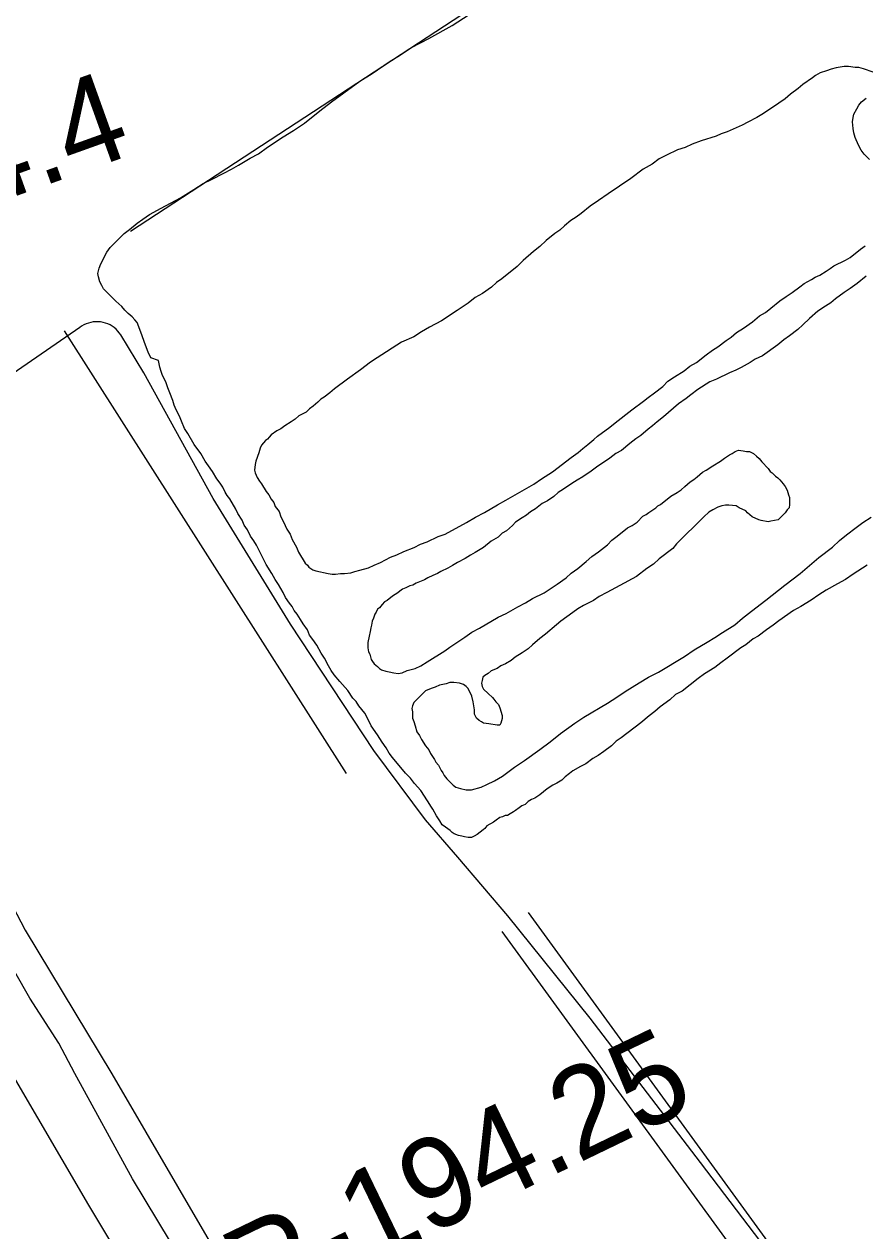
# Model space of a CAD drawing. Extents: x 3324125 to 3362000, y 600753 to 626151.
# Drawn here: x 3331430 to 3332206, y 613099 to 614214 of the extents above; entities that cross this region are included whole.
import ezdxf

# ---------------------------------------------------------------- set-up
doc = ezdxf.new("R2010")
doc.units = 0
for name, color, linetype in [('V-DTCH-CNTR', 7, 'Continuous'), ('V-RIVR-RANG-IDEN', 7, 'Continuous'), ('V-ROAD-CNTR', 7, 'Continuous'), ('V-SITE-VEGE', 7, 'Continuous'), ('V-TOPO-SHOR', 7, 'Continuous')]:
    doc.layers.add(name, color=color, linetype=linetype)

msp = doc.modelspace()

# ---------------------------------------------------------------- linework, layer by layer
at = {"layer": 'V-DTCH-CNTR'}
for points in [[(3330957.7, 614274.3), (3331010.7, 614177.8), (3331082.2, 614037.5), (3331152.6, 613902.5), (3331209.1, 613797.3), (3331231.5, 613760.5), (3331290.9, 613648.4), (3331372.2, 613487.5), (3331430.4, 613376.6), (3331510.5, 613243.8), (3331602.7, 613085.8)], [(3332148.2, 613038.2), (3332054.3, 613161.7), (3331952.4, 613295), (3331876.3, 613389.8), (3331830.2, 613443.8), (3331800.3, 613478.3), (3331752.5, 613542.6), (3331675.6, 613659.3), (3331604.1, 613775.3), (3331540.1, 613891.4), (3331518.8, 613926.5), (3331517.5, 613928.4), (3331516.1, 613930.1), (3331514.5, 613931.8), (3331512.7, 613933.2), (3331510.9, 613934.6), (3331508.9, 613935.7), (3331506.8, 613936.7), (3331504.7, 613937.5), (3331502.5, 613938.1), (3331500.2, 613938.5), (3331498, 613938.7), (3331495.7, 613938.7), (3331493.4, 613938.5), (3331491.1, 613938.1), (3331488.9, 613937.5), (3331486.8, 613936.8), (3331484.7, 613935.8), (3331482.7, 613934.6), (3331480.9, 613933.3), (3331307.9, 613814.1)]]:
    msp.add_lwpolyline(points, dxfattribs=at)
at = {"layer": 'V-ROAD-CNTR'}
for points in [[(3328654.4, 618531.3), (3329365.9, 617157.1), (3329945, 616043.4), (3330528.3, 614922), (3330989.5, 614026.8), (3331101.4, 613813.5), (3331202.1, 613623.7), (3331288.2, 613468), (3331370, 613325.9), (3331489, 613122.4), (3331566.5, 612992.9), (3331683.8, 612804.9), (3331896.1, 612486.7), (3332030.8, 612296.1), (3332261.4, 611985.3), (3332414.1, 611792.3), (3332593.4, 611567.9), (3332751.8, 611383.2), (3332947.9, 611162.2), (3333176.2, 610911.4), (3333408.7, 610672.1), (3333754.4, 610344.1), (3333997.3, 610124.4), (3334416.3, 609777.9)], [(3331895.2, 613392.7), (3332218.1, 612948.7)], [(3331870.9, 613375.1), (3332194, 612930.9)]]:
    msp.add_lwpolyline(points, dxfattribs=at)
at = {"layer": 'V-SITE-VEGE'}
for points in [[(3331603.5, 613800.2), (3331599.9, 613805.5), (3331596.9, 613809.7), (3331592.7, 613816.9), (3331586.7, 613825.2), (3331580.8, 613835.4), (3331577.8, 613840.1), (3331574.8, 613846.7), (3331573, 613851.5), (3331570, 613857.4), (3331568.2, 613861.6), (3331567, 613865.8), (3331564, 613872.9), (3331562.2, 613877.7), (3331560.4, 613883.1), (3331557.4, 613889.1), (3331556.2, 613892.6), (3331555, 613896.8), (3331553.8, 613902.8), (3331546.6, 613905.2), (3331544.2, 613910.5), (3331540.6, 613919.5), (3331538.2, 613926.6), (3331534.1, 613938), (3331531.7, 613940.4), (3331529.3, 613943.3), (3331525.7, 613946.3), (3331522.7, 613949.3), (3331519.7, 613952.9), (3331514.3, 613957.7), (3331503, 613969), (3331501.2, 613972), (3331499.4, 613975.5), (3331498.2, 613980.3), (3331497.6, 613983.3), (3331498.8, 613988.1), (3331500.5, 613992.3), (3331505.9, 614003), (3331508.9, 614007.2), (3331522, 614020.3), (3331526.8, 614023.9), (3331533.9, 614029.9), (3331539.3, 614033.5), (3331545.3, 614037.7), (3331556, 614043.7), (3331573.9, 614053.2), (3331586.4, 614061), (3331594.8, 614066.4), (3331602.5, 614070), (3331613.9, 614076), (3331621, 614079.6), (3331627.6, 614083.2), (3331638.3, 614089.7), (3331646.1, 614093.9), (3331654.4, 614099.9), (3331668.7, 614109.5), (3331678.3, 614115.5), (3331688.4, 614122.1), (3331702.7, 614133.4), (3331713.5, 614141.8), (3331739.7, 614160.9), (3331751.1, 614168.1), (3331766.6, 614178.9), (3331777.3, 614185.4), (3331787.4, 614192), (3331803.5, 614200.4), (3331825, 614212.4), (3331840.5, 614222.5)], [(3332213.7, 614169.3), (3332204.8, 614172.3), (3332200.6, 614173.5), (3332197, 614173.5), (3332191, 614174.6), (3332186.8, 614174.6), (3332179.7, 614173.4), (3332174.9, 614172.2), (3332170.7, 614170.4), (3332164.8, 614168.6), (3332160.6, 614166.3), (3332157.6, 614163.9), (3332148.7, 614157.9), (3332144.5, 614154.3), (3332137.3, 614148.9), (3332132.6, 614144.7), (3332126.6, 614140.5), (3332112.3, 614131), (3332106.3, 614127.4), (3332098, 614123.2), (3332092.6, 614120.2), (3332078.9, 614114.2), (3332073.5, 614112.4), (3332068.7, 614110), (3332055, 614105.8), (3332046.6, 614102.8), (3332040.1, 614099.8), (3332032.9, 614097.4), (3332022.8, 614092.6), (3332016.2, 614089.1), (3332009.7, 614084.3), (3332001.3, 614079.5), (3331990, 614071.1)], [(3332210.2, 614088.7), (3332205.5, 614093.5), (3332202.5, 614097.1), (3332200.1, 614101.8), (3332197.1, 614109), (3332195.9, 614113.2), (3332195.3, 614117.3), (3332194.7, 614123.3), (3332195.3, 614127.5), (3332195.9, 614130.5), (3332198.8, 614135.3), (3332200.6, 614138.8), (3332203, 614141.8), (3332207.2, 614145.4)], [(3331990, 614071.1), (3331969.1, 614056.8), (3331960.1, 614050.8), (3331952.4, 614045.4), (3331944, 614038.8), (3331939.3, 614035.2), (3331934.5, 614032.2), (3331928.5, 614027.4), (3331924.4, 614023.3), (3331919.6, 614020.3), (3331911.8, 614013.7), (3331905.9, 614008.3), (3331899.9, 614003.5), (3331890.4, 613995.2), (3331885, 613989.8), (3331870.7, 613978.4), (3331865.9, 613974.8), (3331861.2, 613970.6), (3331852.8, 613964.7), (3331846.2, 613961.1), (3331839.7, 613955.7), (3331829.5, 613949.1), (3331815.2, 613939.5), (3331803.9, 613933.6), (3331796.7, 613929.4), (3331789.6, 613924.6), (3331778.2, 613919.8), (3331755.6, 613905.4), (3331749.6, 613901.2), (3331740.1, 613894.1), (3331728.1, 613885.7), (3331716.2, 613876.7), (3331712, 613873.1), (3331706.7, 613869), (3331703.7, 613867.2), (3331700.7, 613864.2), (3331696.5, 613860.6), (3331693, 613858.2), (3331690, 613855.2), (3331683.4, 613851.6), (3331679.8, 613848.6), (3331676.3, 613846.2), (3331670.3, 613842.6), (3331666.7, 613839.7), (3331663.1, 613837.9), (3331657.8, 613834.3), (3331656, 613831.9), (3331654.2, 613830.1), (3331652.4, 613828.9), (3331648.8, 613824.7), (3331647.6, 613821.7), (3331646.4, 613817.5), (3331643.5, 613809.8), (3331642.9, 613806.8), (3331642.3, 613801.4), (3331642.9, 613799), (3331644.7, 613794.8), (3331647.1, 613791.3), (3331648.9, 613788.9), (3331653.1, 613781.7), (3331655.5, 613778.7), (3331657.8, 613774.6), (3331660.2, 613771.6), (3331661.4, 613768), (3331665, 613763.2), (3331666.8, 613758.5), (3331669.2, 613753.7), (3331672.2, 613747.1), (3331675.2, 613742.4), (3331677, 613737.6), (3331681.2, 613730.4), (3331683, 613725.7), (3331689, 613715.5), (3331691.4, 613713.7), (3331692.5, 613711.9), (3331696.1, 613709.5), (3331699.1, 613708.4), (3331710.5, 613706), (3331714, 613705.4), (3331717, 613705.4), (3331721.8, 613706), (3331725.4, 613706), (3331731.4, 613706.6), (3331734.9, 613707.8), (3331739.7, 613709), (3331747.5, 613711.4), (3331752.8, 613713.8), (3331758.8, 613716.2), (3331767.8, 613721), (3331773.7, 613723.4), (3331780.3, 613726.4), (3331789.8, 613730), (3331795.8, 613733), (3331801.8, 613735.4), (3331811.9, 613740.1), (3331818.5, 613742.5), (3331838.2, 613753.3), (3331846.5, 613758.1), (3331854.9, 613762.3), (3331866.8, 613769.5), (3331874.5, 613773.7)], [(3331874.5, 613773.7), (3331900.2, 613788.6), (3331907.4, 613793.4), (3331917.5, 613800), (3331934.8, 613813.1), (3331941.3, 613817.9), (3331945.5, 613821.5), (3331950.3, 613825.1), (3331955.7, 613829.9), (3331959.2, 613832.9), (3331970.6, 613841.2), (3331975.3, 613845.4), (3331990.8, 613857.4), (3332001.6, 613865.2), (3332005.8, 613868.8), (3332011.7, 613872.9), (3332019.5, 613878.9), (3332024.2, 613883.7), (3332030.2, 613887.9), (3332039.2, 613893.3), (3332044.5, 613897.5), (3332050.5, 613901), (3332059.4, 613908.2), (3332065.4, 613912.4), (3332070.2, 613915.4), (3332077.9, 613921.4), (3332082.7, 613924.4), (3332087.5, 613928.6), (3332094, 613932.7), (3332102.4, 613938.7), (3332108.9, 613944.1), (3332114.3, 613947.1), (3332119.1, 613951.3), (3332127.4, 613957.9), (3332133.4, 613962), (3332138.8, 613965.6), (3332145.9, 613971), (3332150.1, 613974), (3332156.7, 613977.6), (3332160.2, 613980), (3332164.4, 613981.8), (3332170.4, 613985.4), (3332174, 613987.8), (3332177.5, 613990.2), (3332188.3, 613995.6), (3332192.4, 613997.9), (3332202, 614005.7), (3332206.2, 614008.7)], [(3332207.4, 613980.7), (3332199, 613974.1), (3332192.5, 613969.3), (3332187.1, 613965.7), (3332178.8, 613959.7), (3332174.6, 613956.1), (3332169.8, 613953.1), (3332162.7, 613948.4), (3332154.9, 613941.8), (3332148.9, 613935.8), (3332144.2, 613931.6), (3332136.4, 613925.6), (3332131.1, 613922), (3332125.7, 613917.3), (3332111.4, 613907.1), (3332104.8, 613904.1), (3332100, 613901.1), (3332091.7, 613896.3), (3332086.9, 613893.9), (3332080.9, 613891.5), (3332069, 613885.6), (3332063, 613883.2), (3332051.7, 613876), (3332045.2, 613871.2), (3332041, 613867.6), (3332033.8, 613862.8), (3332020.1, 613850.9), (3332014.1, 613846.1), (3332010, 613842.5), (3332005.8, 613839.5), (3331999.2, 613833.5), (3331994.5, 613830.5)], [(3331994.5, 613830.5), (3331989.1, 613826.3), (3331981.3, 613819.8), (3331976, 613816.8), (3331970.6, 613812.6), (3331958.1, 613804.2), (3331953.3, 613800.6), (3331945.6, 613795.2), (3331940.2, 613792.3), (3331935.4, 613789.3), (3331927.7, 613783.9), (3331922.9, 613780.9), (3331918.7, 613777.3), (3331912.8, 613773.1), (3331908, 613770.7), (3331902, 613765.9), (3331897.2, 613762.9), (3331893.7, 613760), (3331889.5, 613757.6), (3331883.5, 613753.4), (3331880.5, 613750.4), (3331875.2, 613745.6), (3331871, 613743.2), (3331867.4, 613739.6), (3331860.9, 613736), (3331853.7, 613730.1), (3331846, 613725.3), (3331841.8, 613722.9), (3331837, 613719.9), (3331829.8, 613716.3), (3331825.1, 613713.3), (3331820.9, 613710.9), (3331814.3, 613707.9), (3331811.4, 613706.1), (3331807.2, 613704.3), (3331802.4, 613701.9), (3331799.4, 613700.1), (3331791.7, 613697.1), (3331788.7, 613695.3), (3331785.7, 613694.7), (3331782.1, 613692.9), (3331779.1, 613691.7), (3331773.8, 613687.6), (3331770.8, 613685.8), (3331768.4, 613684), (3331764.8, 613681), (3331762.4, 613679.8), (3331760.1, 613677.4), (3331757.7, 613674.4), (3331755.9, 613673.2), (3331754.7, 613670.2), (3331753.5, 613668.4), (3331752.3, 613664.9), (3331751.1, 613661.9), (3331750.5, 613658.3), (3331749.9, 613655.9), (3331749.3, 613652.3), (3331748.2, 613648.1), (3331747, 613642.2), (3331747, 613637.4), (3331747.6, 613633.8), (3331748.8, 613631.4), (3331750, 613626.6), (3331751.2, 613624.8), (3331753, 613622.5), (3331755.9, 613620.1), (3331757.7, 613618.3), (3331759.5, 613617.1), (3331763.7, 613615.9), (3331766.7, 613615.3), (3331770.9, 613614.1), (3331775.1, 613613.5), (3331778.6, 613614.1), (3331783.4, 613616.5), (3331790.6, 613618.3), (3331795.9, 613620.7), (3331801.9, 613624.3), (3331818, 613634.5), (3331822.8, 613638.1), (3331828.2, 613641.7), (3331836.5, 613647.1), (3331843.1, 613651.8), (3331850.2, 613655.4), (3331867.5, 613665.6), (3331874.7, 613669.2), (3331885.4, 613675.2), (3331892.6, 613678.8), (3331899.1, 613682.9), (3331909.9, 613688.3), (3331916.4, 613692.5), (3331921.8, 613696.1), (3331930.2, 613702.1), (3331934.9, 613706.3), (3331940.9, 613710.5), (3331948.6, 613717), (3331954, 613721.8), (3331960, 613726), (3331968.3, 613732.6), (3331972.5, 613736.8), (3331977.3, 613740.4), (3331986.8, 613748.1)], [(3331986.8, 613748.1), (3331991, 613750.5), (3331995.8, 613753.5), (3332001.1, 613758.9), (3332004.1, 613760.7), (3332006.5, 613762.5), (3332010.1, 613764.9), (3332013.1, 613766.7), (3332014.8, 613768.5), (3332017.2, 613769.7), (3332026.8, 613777.4), (3332032.7, 613781), (3332036.3, 613783.4), (3332039.9, 613786.4), (3332044.7, 613790.6), (3332048.2, 613793), (3332051.2, 613795.4), (3332056, 613799.6), (3332059.6, 613801.4), (3332065.5, 613805.6), (3332072.7, 613809.7), (3332076.3, 613812.7), (3332081, 613815.7), (3332083.4, 613816.9), (3332086.4, 613818.7), (3332089.4, 613819.9), (3332093.6, 613819.3), (3332096.6, 613818.7), (3332099.6, 613818.7), (3332103.1, 613816.9), (3332106.1, 613814.6), (3332108.5, 613812.2), (3332110.9, 613809.2), (3332116.9, 613803.2), (3332118.7, 613800.2), (3332120.5, 613799.1), (3332123.5, 613796.1), (3332125.8, 613794.3), (3332127.6, 613792.5), (3332130.6, 613788.9), (3332132.4, 613786.5), (3332134.2, 613783), (3332135.4, 613778.8), (3332136.6, 613776.4), (3332136.6, 613769.8), (3332136, 613766.8), (3332134.2, 613765), (3332132.5, 613762.1), (3332125.9, 613755.5), (3332119.3, 613754.3), (3332116.9, 613753.7), (3332110.4, 613754.9), (3332108, 613755.5), (3332102, 613758.4), (3332097.8, 613762), (3332096, 613763.8), (3332090.1, 613766.8), (3332087.1, 613768.6), (3332080.5, 613769.2), (3332077.5, 613769.1), (3332073.9, 613768.5), (3332070.4, 613767.3), (3332065.6, 613765), (3332062, 613762.6), (3332057.2, 613758.4), (3332032.2, 613733.3), (3332028.6, 613729.1), (3332016.1, 613719.5), (3332010.7, 613714.7), (3332004.8, 613710.6), (3331995.2, 613703.4), (3331979.7, 613695), (3331967.8, 613688.4), (3331960.6, 613684.8), (3331955.3, 613681.2), (3331946.3, 613676.4), (3331940.9, 613673.5), (3331936.2, 613669.9), (3331925.4, 613662.1), (3331921.3, 613658.5), (3331911.1, 613650.1), (3331905.8, 613645.9), (3331899.2, 613640), (3331895, 613636.4), (3331889.7, 613632.8), (3331883.1, 613628.6), (3331879.5, 613625.6), (3331874.1, 613622.6), (3331870, 613620.8), (3331866.4, 613618.4), (3331861, 613616), (3331858, 613613.6), (3331855.1, 613611.9), (3331853.3, 613610.1), (3331852.7, 613607.1), (3331852.1, 613604.7), (3331852.7, 613601.7), (3331853.9, 613599.3), (3331858.1, 613595.1), (3331862.3, 613591.6), (3331863.4, 613589.8)], [(3331965, 613541.6), (3331959.6, 613538), (3331954.9, 613535), (3331948.3, 613530.2), (3331943.5, 613527.8), (3331936.4, 613523.6), (3331933.4, 613521.2), (3331929.2, 613518.2), (3331926.2, 613515.2), (3331921.5, 613512.2), (3331917.9, 613510.4), (3331912.5, 613506.9), (3331905.9, 613501.5), (3331901.2, 613498.5), (3331898.2, 613497.3), (3331895.2, 613495.5), (3331892.2, 613492.5), (3331889.2, 613491.3), (3331886.9, 613489.5), (3331883.3, 613487.1), (3331881.5, 613485.9), (3331878.5, 613484.1), (3331876.1, 613482.3), (3331873.7, 613482.3), (3331871.4, 613481.1), (3331869, 613480.5), (3331865.4, 613478.1), (3331863, 613476.3), (3331857, 613472.8), (3331855.2, 613470.4), (3331853.5, 613469.2), (3331848.1, 613465), (3331845.1, 613463.2), (3331842.7, 613462), (3331839.7, 613462), (3331836.2, 613462.6), (3331833.8, 613463.2), (3331830.8, 613463.8), (3331826.6, 613465.6), (3331824.8, 613466.7), (3331823, 613468.5), (3331818.8, 613471.5), (3331815.8, 613473.9), (3331813.4, 613477.5), (3331810.5, 613482.2), (3331806.9, 613488.2), (3331805.7, 613490), (3331802.1, 613496), (3331796.1, 613505.5), (3331790.1, 613512.1), (3331786.5, 613516.8), (3331781.8, 613521.6), (3331769.8, 613535.9), (3331766.8, 613540.1), (3331763.8, 613544.9), (3331760.2, 613550.2), (3331756, 613556.8), (3331750.1, 613565.2), (3331747.1, 613571.7), (3331744.1, 613577.1), (3331738.7, 613583.6), (3331736.3, 613587.8), (3331733.3, 613590.8), (3331728.5, 613598), (3331721.3, 613606.3), (3331716, 613612.3), (3331713, 613616.4), (3331710.6, 613620.6), (3331707, 613627.8), (3331704, 613632.5), (3331699.8, 613639.7), (3331696.2, 613645.1), (3331693.2, 613649.2), (3331691.4, 613654), (3331687.2, 613659.4), (3331684.9, 613663.6), (3331681.9, 613668.3), (3331678.9, 613671.9), (3331677.1, 613675.5), (3331674.7, 613678.5), (3331671.1, 613683.8), (3331668.7, 613688.6), (3331664.5, 613695.8), (3331661.5, 613700.5), (3331658.5, 613705.9), (3331653.1, 613714.3), (3331644.2, 613732.2), (3331641.8, 613736.3), (3331638.8, 613740.5), (3331635.8, 613746.5), (3331632.8, 613750.7), (3331631, 613755.4), (3331626.8, 613761.4), (3331625, 613765.6), (3331619.6, 613775.1), (3331617.2, 613778.1), (3331615.4, 613781.1), (3331613.1, 613785.9), (3331610.7, 613789.4), (3331607.7, 613793.6), (3331603.5, 613800.2)], [(3331863.4, 613589.8), (3331865.2, 613587.4), (3331867.6, 613585), (3331868.8, 613582), (3331871.2, 613574.9), (3331871.2, 613571.9), (3331870, 613567.7), (3331868.9, 613565.9), (3331866.5, 613565.9), (3331858.7, 613567.1), (3331853.9, 613567.7), (3331852.1, 613568.9), (3331849.7, 613570.1), (3331847.4, 613572.4), (3331845.6, 613576), (3331845.5, 613580.2), (3331844.3, 613587.4), (3331843.1, 613592.7), (3331839.6, 613599.9), (3331837.8, 613601.7), (3331835.4, 613603.5), (3331831.8, 613604.7), (3331826.4, 613605.2), (3331822.8, 613605.2), (3331819.3, 613604), (3331813.3, 613602.8), (3331809.1, 613601), (3331805.5, 613599.8), (3331800.2, 613597.5), (3331789.4, 613586.7), (3331788.2, 613583.7), (3331787.6, 613581.3), (3331788.2, 613578.3), (3331788.2, 613572.4), (3331789.4, 613569.4), (3331790.6, 613565.2), (3331792.4, 613559.8), (3331794.8, 613556.3), (3331796.6, 613552.7), (3331800.2, 613546.7), (3331803.2, 613543.1), (3331805, 613539.6), (3331808.6, 613534.2), (3331809.8, 613531.8), (3331812.2, 613528.8), (3331814.6, 613524), (3331816.4, 613521.7), (3331817.6, 613519.3), (3331820, 613516.3), (3331825.9, 613510.3), (3331828.3, 613508.5), (3331832.5, 613507.4), (3331837.9, 613506.2), (3331842.7, 613506.2), (3331851.6, 613508.6), (3331857, 613511), (3331864.1, 613514.6), (3331871.3, 613518.7), (3331882.6, 613527.1), (3331891.6, 613533.1), (3331905.9, 613543.3), (3331915.4, 613550.4), (3331925, 613558.2), (3331938.1, 613567.8), (3331946.4, 613573.2), (3331968.5, 613586.3), (3331976.9, 613591.7), (3331984.6, 613597.1), (3331997.7, 613604.9), (3332006.1, 613610.3), (3332015.6, 613615), (3332039.5, 613629.4), (3332048.5, 613635.4), (3332060.4, 613642.6), (3332067.5, 613646.8), (3332074.7, 613651.5), (3332086, 613658.7), (3332093.2, 613664.7), (3332101.5, 613671.3), (3332114.7, 613681.4), (3332132, 613695.2), (3332146.3, 613706), (3332163.6, 613720.9), (3332176.1, 613730.5), (3332182.6, 613736.5), (3332189.2, 613741.8), (3332198.1, 613748.4), (3332204.1, 613753.2), (3332211.9, 613758)], [(3332208.3, 613713.8), (3332195.2, 613705.4), (3332188.1, 613700.6), (3332180.9, 613696.5), (3332170.2, 613690.5), (3332163.6, 613686.3), (3332156.4, 613681.5), (3332146.9, 613675.5), (3332140.3, 613671.9), (3332126.6, 613662.4), (3332121.3, 613658.2), (3332115.3, 613654), (3332107.5, 613648), (3332102.8, 613645.6), (3332096.2, 613640.2), (3332091.4, 613637.2), (3332078.9, 613627.7), (3332072.9, 613623.5), (3332067.6, 613619.3), (3332058, 613613.3), (3332052.1, 613609.1), (3332037.2, 613597.2), (3332031.2, 613594.2), (3332025.8, 613589.4), (3332016.9, 613582.8), (3332012.1, 613578.6), (3332006.7, 613574.4), (3331999, 613567.9), (3331981.1, 613554.1), (3331976.3, 613551.1), (3331972.2, 613546.9), (3331965, 613541.6)]]:
    msp.add_lwpolyline(points, dxfattribs=at)
at = {"layer": 'V-TOPO-SHOR'}
for p, q in [((3331527.7, 614022.3), (3332519.7, 614671.7)), ((3331466.4, 613930.3), (3331727.1, 613521.2))]:
    msp.add_line(p, q, dxfattribs=at)
msp.add_lwpolyline([(3331854.7, 612684.6), (3331838.4, 612673.6), (3331836.3, 612674.3), (3331751, 612789.3), (3331652.7, 612945.9), (3331632.2, 612984.7), (3331598.8, 613031.7), (3331529.8, 613146.7), (3331476.5, 613244.1), (3331461.5, 613272), (3331434.9, 613313.5), (3331395.3, 613382.2), (3331364.6, 613438.8), (3331350.9, 613463.9), (3331317.5, 613516.4), (3331249.8, 613645.7), (3331183.6, 613768.2), (3331105.7, 613911.2), (3331033.3, 614056.9), (3330977.3, 614172.6), (3330936.3, 614253.7)], dxfattribs=at)

# ---------------------------------------------------------------- texts
at = {"layer": 'V-RIVR-RANG-IDEN'}
for s, rotation, p in [('R-194.4', 19.7253, (3331160.3, 613960.9)), ('R-194.25', 25.7857, (3331641.1, 613015.9))]:
    msp.add_text(s, height=83, rotation=rotation, dxfattribs=at).set_placement(p)

doc.saveas('drawing.dxf')
